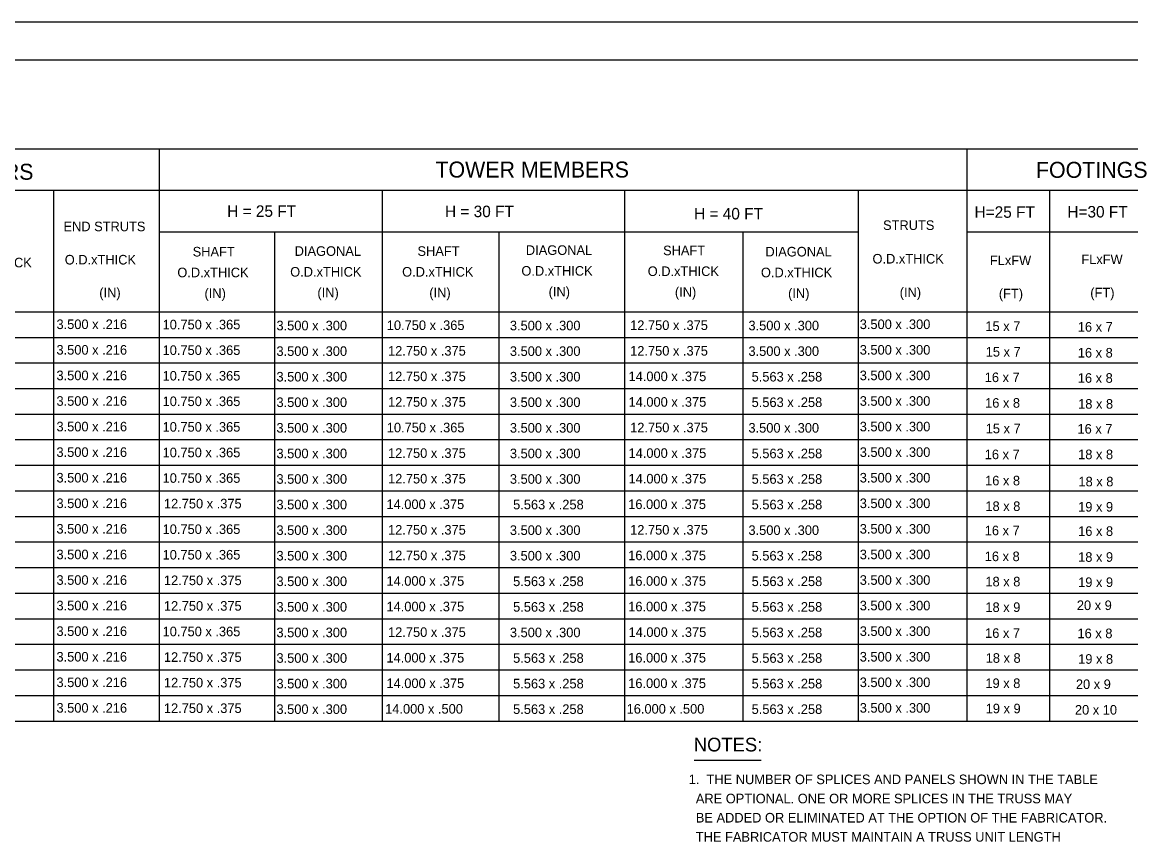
# Model space of a CAD drawing. Extents: x -3 to 26050223, y 0 to 12035012.
# Drawn here: x 14.2 to 43.09, y 21.96 to 43.33 of the extents above; entities that cross this region are included whole.
import ezdxf

# ---------------------------------------------------------------- set-up
doc = ezdxf.new("R2010")
doc.units = 0
for name, color, linetype in [('1', 7, 'Continuous'), ('2', 7, 'Continuous'), ('39', 7, 'Continuous')]:
    doc.layers.add(name, color=color, linetype=linetype)

msp = doc.modelspace()

# ---------------------------------------------------------------- linework, layer by layer
at = {"layer": '1'}
for p, q in [((68.892, 43.325), (0, 43.325)), ((4, 40.025), (17.775, 40.025)), ((17.775, 25.108), (17.775, 40.025)), ((17.775, 40.025), (67.875, 40.025)), ((38.825, 25.108), (38.825, 40.025)), ((6.55, 38.942), (17.775, 38.942)), ((15.025, 25.083), (15.025, 38.917)), ((17.775, 38.942), (65.125, 38.942)), ((23.592, 25.108), (23.592, 38.942)), ((29.9, 25.108), (29.9, 38.942)), ((35.992, 25.108), (35.992, 38.942)), ((40.983, 25.108), (40.983, 38.942)), ((17.775, 37.858), (35.992, 37.858)), ((20.783, 25.108), (20.783, 37.858)), ((26.633, 25.108), (26.633, 37.858)), ((32.983, 25.108), (32.983, 37.858)), ((38.825, 37.858), (65.125, 37.858)), ((3.979, 35.775), (20.692, 35.775)), ((20.692, 35.775), (67.875, 35.775)), ((6.55, 35.108), (20.692, 35.108)), ((20.692, 35.108), (65.125, 35.108)), ((6.55, 34.442), (20.692, 34.442)), ((20.692, 34.442), (65.125, 34.442)), ((6.55, 33.775), (20.692, 33.775)), ((20.692, 33.775), (65.125, 33.775)), ((6.55, 33.108), (20.692, 33.108)), ((20.692, 33.108), (65.125, 33.108)), ((6.55, 32.442), (20.692, 32.442)), ((20.692, 32.442), (65.125, 32.442)), ((6.55, 31.775), (20.692, 31.775)), ((20.692, 31.775), (65.125, 31.775)), ((6.55, 31.108), (20.758, 31.108)), ((20.692, 31.108), (65.125, 31.108)), ((6.55, 30.442), (20.758, 30.442)), ((20.692, 30.442), (65.125, 30.442)), ((6.55, 29.775), (20.758, 29.775)), ((20.692, 29.775), (65.125, 29.775)), ((6.55, 29.108), (20.758, 29.108)), ((20.692, 29.108), (65.125, 29.108)), ((6.55, 28.442), (20.758, 28.442)), ((20.692, 28.442), (65.125, 28.442)), ((6.55, 27.775), (20.758, 27.775)), ((20.692, 27.775), (65.125, 27.775)), ((6.55, 27.108), (20.758, 27.108)), ((20.692, 27.108), (65.125, 27.108)), ((6.55, 26.442), (20.758, 26.442)), ((20.692, 26.442), (65.125, 26.442)), ((6.55, 25.775), (20.758, 25.775)), ((20.692, 25.775), (65.125, 25.775)), ((3.979, 25.108), (20.758, 25.108)), ((20.692, 25.108), (67.867, 25.108))]:
    msp.add_line(p, q, dxfattribs=at)
at = {"layer": '2'}
msp.add_line((31.709, 24.089), (33.459, 24.089), dxfattribs=at)
at = {"layer": '39'}
msp.add_line((3.6, 42.342), (68.183, 42.342), dxfattribs=at)

# ---------------------------------------------------------------- texts
at = {"layer": '1'}
for s, height, p in [('TRUSS MEMBERS', 0.41665, (9.633, 39.217)), ('TOWER MEMBERS', 0.41665, (24.967, 39.275)), ('FOOTINGS', 0.4166, (40.617, 39.267)), ('H = 25 FT', 0.3, (19.542, 38.25)), ('H = 30 FT', 0.3, (25.217, 38.242)), ('H = 40 FT', 0.3, (31.708, 38.183)), ('H=25 FT', 0.3, (39.017, 38.225)), ('H=30 FT', 0.3, (41.435, 38.233)), ('STRUTS', 0.25, (36.633, 37.908)), ('END STRUTS', 0.25, (15.275, 37.875)), ('SHAFT', 0.25, (18.642, 37.217)), ('DIAGONAL', 0.25, (21.3, 37.233)), ('SHAFT', 0.25, (24.5, 37.233)), ('DIAGONAL', 0.25, (27.325, 37.258)), ('SHAFT', 0.25, (30.9, 37.25)), ('DIAGONAL', 0.25, (33.567, 37.217)), ('O.D.xTHICK', 0.25, (36.358, 37.033)), ('O.D.xTHICK', 0.25, (12.592, 36.933)), ('O.D.xTHICK', 0.25, (15.308, 37.008)), ('FLxFW', 0.25, (39.417, 36.992)), ('FLxFW', 0.25, (41.8, 37.017)), ('O.D.xTHICK', 0.25, (18.242, 36.675)), ('O.D.xTHICK', 0.25, (21.183, 36.692)), ('O.D.xTHICK', 0.25, (24.1, 36.692)), ('O.D.xTHICK', 0.25, (27.208, 36.717)), ('O.D.xTHICK', 0.25, (30.5, 36.708)), ('O.D.xTHICK', 0.25, (33.45, 36.675)), ('(IN)', 0.25, (16.208, 36.15)), ('(IN)', 0.25, (21.892, 36.15)), ('(IN)', 0.25, (24.808, 36.15)), ('(IN)', 0.25, (27.917, 36.175)), ('(IN)', 0.25, (31.208, 36.167)), ('(IN)', 0.25, (37.067, 36.158)), ('(FT)', 0.25, (42.033, 36.15)), ('(IN)', 0.25, (18.95, 36.133)), ('(IN)', 0.25, (34.158, 36.133)), ('(FT)', 0.25, (39.65, 36.125)), ('3.500 x .216', 0.25, (15.092, 35.325)), ('10.750 x .365', 0.25, (17.858, 35.317)), ('3.500 x .300', 0.25, (20.825, 35.292)), ('10.750 x .365', 0.25, (23.7, 35.3)), ('3.500 x .300', 0.25, (26.908, 35.292)), ('12.750 x .375', 0.25, (30.042, 35.3)), ('3.500 x .300', 0.25, (33.125, 35.292)), ('3.500 x .300', 0.25, (36.025, 35.325)), ('15 x 7', 0.25, (39.3, 35.275)), ('16 x 7', 0.25, (41.708, 35.258)), ('3.500 x .216', 0.25, (15.092, 34.658)), ('10.750 x .365', 0.25, (17.858, 34.65)), ('3.500 x .300', 0.25, (20.825, 34.625)), ('12.750 x .375', 0.25, (23.733, 34.633)), ('3.500 x .300', 0.25, (26.908, 34.625)), ('12.750 x .375', 0.25, (30.042, 34.633)), ('3.500 x .300', 0.25, (33.125, 34.625)), ('3.500 x .300', 0.25, (36.025, 34.658)), ('15 x 7', 0.25, (39.308, 34.608)), ('16 x 8', 0.25, (41.708, 34.583)), ('3.500 x .216', 0.25, (15.092, 33.992)), ('10.750 x .365', 0.25, (17.858, 33.983)), ('3.500 x .300', 0.25, (20.825, 33.958)), ('12.750 x .375', 0.25, (23.733, 33.967)), ('3.500 x .300', 0.25, (26.908, 33.958)), ('14.000 x .375', 0.25, (30, 33.967)), ('5.563 x .258', 0.25, (33.208, 33.958)), ('3.500 x .300', 0.25, (36.025, 33.992)), ('16 x 7', 0.25, (39.283, 33.942)), ('16 x 8', 0.25, (41.708, 33.925)), ('3.500 x .216', 0.25, (15.092, 33.325)), ('10.750 x .365', 0.25, (17.858, 33.317)), ('3.500 x .300', 0.25, (20.825, 33.292)), ('12.750 x .375', 0.25, (23.733, 33.3)), ('3.500 x .300', 0.25, (26.908, 33.292)), ('14.000 x .375', 0.25, (30, 33.3)), ('5.563 x .258', 0.25, (33.208, 33.292)), ('3.500 x .300', 0.25, (36.025, 33.325)), ('16 x 8', 0.25, (39.292, 33.275)), ('18 x 8', 0.25, (41.717, 33.25)), ('3.500 x .216', 0.25, (15.092, 32.658)), ('10.750 x .365', 0.25, (17.858, 32.65)), ('3.500 x .300', 0.25, (20.825, 32.625)), ('10.750 x .365', 0.25, (23.7, 32.633)), ('3.500 x .300', 0.25, (26.908, 32.625)), ('12.750 x .375', 0.25, (30.042, 32.633)), ('3.500 x .300', 0.25, (33.125, 32.625)), ('3.500 x .300', 0.25, (36.025, 32.658)), ('15 x 7', 0.25, (39.308, 32.608)), ('16 x 7', 0.25, (41.7, 32.6)), ('3.500 x .216', 0.25, (15.092, 31.992)), ('10.750 x .365', 0.25, (17.858, 31.983)), ('3.500 x .300', 0.25, (20.825, 31.958)), ('12.750 x .375', 0.25, (23.733, 31.967)), ('3.500 x .300', 0.25, (26.908, 31.958)), ('14.000 x .375', 0.25, (30, 31.967)), ('5.563 x .258', 0.25, (33.208, 31.958)), ('3.500 x .300', 0.25, (36.025, 31.992)), ('16 x 7', 0.25, (39.283, 31.933)), ('18 x 8', 0.25, (41.717, 31.933)), ('3.500 x .216', 0.25, (15.092, 31.325)), ('10.750 x .365', 0.25, (17.858, 31.317)), ('3.500 x .300', 0.25, (20.825, 31.292)), ('12.750 x .375', 0.25, (23.733, 31.3)), ('3.500 x .300', 0.25, (26.908, 31.292)), ('14.000 x .375', 0.25, (30, 31.3)), ('5.563 x .258', 0.25, (33.208, 31.292)), ('3.500 x .300', 0.25, (36.025, 31.325)), ('16 x 8', 0.25, (39.292, 31.25)), ('18 x 8', 0.25, (41.725, 31.225)), ('3.500 x .216', 0.25, (15.092, 30.658)), ('12.750 x .375', 0.25, (17.892, 30.65)), ('3.500 x .300', 0.25, (20.825, 30.625)), ('14.000 x .375', 0.25, (23.692, 30.633)), ('5.563 x .258', 0.25, (26.992, 30.625)), ('16.000 x .375', 0.25, (29.992, 30.633)), ('5.563 x .258', 0.25, (33.208, 30.625)), ('3.500 x .300', 0.25, (36.025, 30.658)), ('18 x 8', 0.25, (39.3, 30.583)), ('19 x 9', 0.25, (41.717, 30.567)), ('3.500 x .216', 0.25, (15.092, 29.992)), ('10.750 x .365', 0.25, (17.858, 29.983)), ('3.500 x .300', 0.25, (20.825, 29.958)), ('12.750 x .375', 0.25, (23.733, 29.967)), ('3.500 x .300', 0.25, (26.908, 29.958)), ('12.750 x .375', 0.25, (30.042, 29.967)), ('3.500 x .300', 0.25, (33.125, 29.958)), ('3.500 x .300', 0.25, (36.025, 29.992)), ('16 x 7', 0.25, (39.283, 29.95)), ('16 x 8', 0.25, (41.717, 29.933)), ('3.500 x .216', 0.25, (15.092, 29.325)), ('10.750 x .365', 0.25, (17.858, 29.317)), ('3.500 x .300', 0.25, (20.825, 29.292)), ('12.750 x .375', 0.25, (23.733, 29.3)), ('3.500 x .300', 0.25, (26.908, 29.292)), ('16.000 x .375', 0.25, (29.992, 29.3)), ('5.563 x .258', 0.25, (33.208, 29.292)), ('3.500 x .300', 0.25, (36.025, 29.325)), ('16 x 8', 0.25, (39.283, 29.275)), ('18 x 9', 0.25, (41.717, 29.258)), ('3.500 x .216', 0.25, (15.092, 28.658)), ('12.750 x .375', 0.25, (17.892, 28.65)), ('3.500 x .300', 0.25, (36.025, 28.658)), ('3.500 x .300', 0.25, (20.825, 28.625)), ('14.000 x .375', 0.25, (23.692, 28.633)), ('5.563 x .258', 0.25, (26.992, 28.625)), ('16.000 x .375', 0.25, (29.992, 28.633)), ('5.563 x .258', 0.25, (33.208, 28.625)), ('18 x 8', 0.25, (39.3, 28.617)), ('19 x 9', 0.25, (41.717, 28.6)), ('3.500 x .216', 0.25, (15.092, 27.992)), ('12.750 x .375', 0.25, (17.892, 27.983)), ('3.500 x .300', 0.25, (20.825, 27.958)), ('14.000 x .375', 0.25, (23.692, 27.967)), ('5.563 x .258', 0.25, (26.992, 27.958)), ('16.000 x .375', 0.25, (29.992, 27.967)), ('5.563 x .258', 0.25, (33.208, 27.958)), ('3.500 x .300', 0.25, (36.025, 27.992)), ('18 x 9', 0.25, (39.3, 27.95)), ('20 x 9', 0.25, (41.683, 28)), ('3.500 x .216', 0.25, (15.092, 27.325)), ('10.750 x .365', 0.25, (17.858, 27.317)), ('3.500 x .300', 0.25, (20.825, 27.292)), ('12.750 x .375', 0.25, (23.733, 27.3)), ('3.500 x .300', 0.25, (26.908, 27.292)), ('14.000 x .375', 0.25, (30, 27.3)), ('5.563 x .258', 0.25, (33.208, 27.292)), ('3.500 x .300', 0.25, (36.025, 27.325)), ('16 x 7', 0.25, (39.292, 27.275)), ('16 x 8', 0.25, (41.7, 27.267)), ('3.500 x .216', 0.25, (15.092, 26.658)), ('12.750 x .375', 0.25, (17.892, 26.65)), ('3.500 x .300', 0.25, (20.825, 26.625)), ('14.000 x .375', 0.25, (23.692, 26.633)), ('5.563 x .258', 0.25, (26.992, 26.625)), ('16.000 x .375', 0.25, (29.992, 26.633)), ('5.563 x .258', 0.25, (33.208, 26.625)), ('3.500 x .300', 0.25, (36.025, 26.658)), ('18 x 8', 0.25, (39.308, 26.625)), ('19 x 8', 0.25, (41.717, 26.6)), ('3.500 x .216', 0.25, (15.092, 25.992)), ('12.750 x .375', 0.25, (17.892, 25.983)), ('3.500 x .300', 0.25, (20.825, 25.958)), ('14.000 x .375', 0.25, (23.692, 25.967)), ('5.563 x .258', 0.25, (26.992, 25.958)), ('16.000 x .375', 0.25, (29.992, 25.967)), ('5.563 x .258', 0.25, (33.208, 25.958)), ('3.500 x .300', 0.25, (36.025, 25.992)), ('19 x 8', 0.25, (39.3, 25.967)), ('20 x 9', 0.25, (41.658, 25.942)), ('3.500 x .216', 0.25, (15.092, 25.325)), ('12.750 x .375', 0.25, (17.892, 25.317)), ('3.500 x .300', 0.25, (20.825, 25.292)), ('14.000 x .500', 0.25, (23.658, 25.3)), ('5.563 x .258', 0.25, (26.992, 25.292)), ('16.000 x .500', 0.25, (29.95, 25.3)), ('5.563 x .258', 0.25, (33.208, 25.292)), ('3.500 x .300', 0.25, (36.025, 25.325)), ('19 x 9', 0.25, (39.308, 25.308)), ('20 x 10', 0.25, (41.633, 25.275))]:
    msp.add_text(s, height=height, dxfattribs=at).set_placement(p)
at = {"layer": '2'}
for s, height, p in [('NOTES:', 0.3584, (31.701, 24.314)), ('1.  THE NUMBER OF SPLICES AND PANELS SHOWN IN THE TABLE', 0.25, (31.568, 23.462)), ('  ARE OPTIONAL. ONE OR MORE SPLICES IN THE TRUSS MAY', 0.25, (31.568, 22.962)), ('  BE ADDED OR ELIMINATED AT THE OPTION OF THE FABRICATOR.', 0.25, (31.568, 22.462)), ('  THE FABRICATOR MUST MAINTAIN A TRUSS UNIT LENGTH', 0.25, (31.568, 21.962))]:
    msp.add_text(s, height=height, dxfattribs=at).set_placement(p)

doc.saveas('drawing.dxf')
